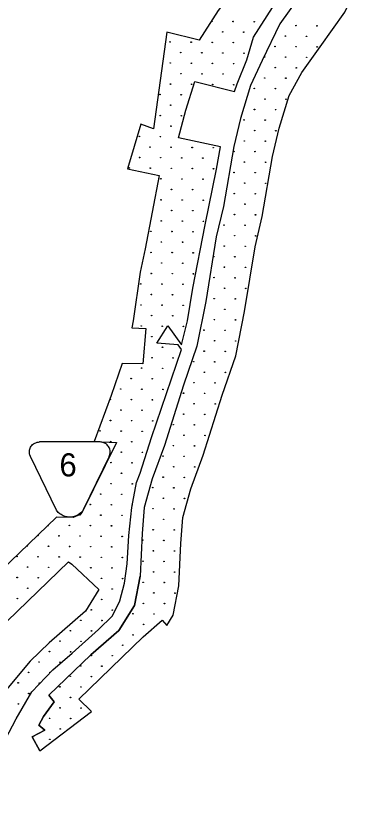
# Model space of a CAD drawing. Extents: x 1612280 to 1883141, y 560852 to 780851.
# Drawn here: x 1737209 to 1743599, y 621707 to 636137 of the extents above; entities that cross this region are included whole.
import ezdxf

# ---------------------------------------------------------------- set-up
doc = ezdxf.new("R2010")
doc.units = 0
for name, color, linetype in [('DESIGN - EROSION CONTROL - Devices', 7, 'Continuous'), ('DESIGN - ROW - Easement Linework and Patterning', 7, 'Continuous'), ('DESIGN - SCRATCH - User 1', 7, 'Continuous')]:
    doc.layers.add(name, color=color, linetype=linetype)

msp = doc.modelspace()

# ---------------------------------------------------------------- linework, layer by layer
at = {"layer": 'DESIGN - EROSION CONTROL - Devices'}
for centre in [(1740788, 636037), (1740788, 636037), (1741172, 636033), (1741172, 636033), (1741557, 636029), (1741557, 636029), (1742317, 635958), (1742317, 635958), (1742701, 635954), (1742701, 635954), (1740982, 635843), (1740982, 635843), (1741366, 635839), (1741366, 635839), (1740022, 635660), (1740022, 635660), (1740407, 635656), (1740407, 635656), (1740791, 635652), (1740791, 635652), (1741176, 635649), (1741176, 635649), (1742126, 635767), (1742126, 635767), (1742511, 635763), (1742511, 635763), (1741936, 635577), (1741936, 635577), (1742320, 635573), (1742320, 635573), (1742705, 635569), (1742705, 635569), (1740216, 635466), (1740216, 635466), (1740601, 635462), (1740601, 635462), (1740985, 635458), (1740985, 635458), (1741370, 635454), (1741370, 635454), (1741745, 635386), (1741745, 635386), (1742130, 635383), (1742130, 635383), (1742514, 635379), (1742514, 635379), (1740026, 635275), (1740026, 635275), (1740411, 635271), (1740411, 635271), (1740795, 635268), (1740795, 635268), (1741180, 635264), (1741180, 635264), (1740220, 635081), (1740220, 635081), (1740605, 635077), (1740605, 635077), (1740989, 635074), (1740989, 635074), (1741940, 635192), (1741940, 635192), (1742324, 635188), (1742324, 635188), (1741749, 635002), (1741749, 635002), (1742134, 634998), (1742134, 634998), (1740030, 634891), (1740030, 634891), (1740414, 634887), (1740414, 634887), (1740799, 634883), (1740799, 634883), (1741183, 634879), (1741183, 634879), (1741559, 634811), (1741559, 634811), (1741943, 634808), (1741943, 634808), (1739839, 634700), (1739839, 634700), (1740224, 634696), (1740224, 634696), (1741753, 634617), (1741753, 634617), (1740033, 634506), (1740033, 634506), (1742137, 634614), (1742137, 634614), (1741562, 634427), (1741562, 634427), (1741947, 634423), (1741947, 634423), (1739843, 634316), (1739843, 634316), (1740228, 634312), (1740228, 634312), (1741372, 634236), (1741372, 634236), (1741757, 634233), (1741757, 634233), (1740037, 634122), (1740037, 634122), (1741566, 634042), (1741566, 634042), (1739462, 633935), (1739462, 633935), (1739847, 633931), (1739847, 633931), (1741951, 634039), (1741951, 634039), (1741376, 633852), (1741376, 633852), (1741760, 633848), (1741760, 633848), (1739656, 633741), (1739656, 633741), (1740041, 633737), (1740041, 633737), (1740425, 633733), (1740425, 633733), (1740810, 633730), (1740810, 633730), (1741185, 633661), (1741185, 633661), (1741570, 633658), (1741570, 633658), (1739466, 633550), (1739466, 633550), (1739850, 633547), (1739850, 633547), (1740235, 633543), (1740235, 633543), (1740620, 633539), (1740620, 633539), (1741379, 633467), (1741379, 633467), (1741764, 633464), (1741764, 633464), (1739276, 633360), (1739276, 633360), (1739660, 633356), (1739660, 633356), (1740045, 633352), (1740045, 633352), (1740429, 633349), (1740429, 633349), (1740814, 633345), (1740814, 633345), (1741189, 633277), (1741189, 633277), (1741574, 633273), (1741574, 633273), (1739854, 633162), (1739854, 633162), (1740239, 633158), (1740239, 633158), (1740623, 633155), (1740623, 633155), (1741383, 633083), (1741383, 633083), (1741768, 633079), (1741768, 633079), (1740048, 632968), (1740048, 632968), (1740433, 632964), (1740433, 632964), (1741193, 632892), (1741193, 632892), (1741577, 632889), (1741577, 632889), (1739858, 632777), (1739858, 632777), (1740243, 632774), (1740243, 632774), (1740627, 632770), (1740627, 632770), (1741387, 632698), (1741387, 632698), (1740052, 632583), (1740052, 632583), (1740437, 632580), (1740437, 632580), (1741197, 632508), (1741197, 632508), (1741581, 632504), (1741581, 632504), (1739862, 632393), (1739862, 632393), (1740246, 632389), (1740246, 632389), (1740631, 632385), (1740631, 632385), (1741006, 632317), (1741006, 632317), (1741391, 632314), (1741391, 632314), (1739671, 632202), (1739671, 632202), (1740056, 632199), (1740056, 632199), (1740440, 632195), (1740440, 632195), (1741200, 632123), (1741200, 632123), (1741585, 632120), (1741585, 632120), (1739865, 632008), (1739865, 632008), (1740250, 632005), (1740250, 632005), (1741010, 631933), (1741010, 631933), (1741394, 631929), (1741394, 631929), (1739675, 631818), (1739675, 631818), (1740060, 631814), (1740060, 631814), (1740444, 631810), (1740444, 631810), (1740819, 631742), (1740819, 631742), (1741204, 631739), (1741204, 631739), (1739869, 631624), (1739869, 631624), (1740254, 631620), (1740254, 631620), (1741014, 631548), (1741014, 631548), (1741398, 631545), (1741398, 631545), (1739679, 631433), (1739679, 631433), (1740063, 631430), (1740063, 631430), (1740448, 631426), (1740448, 631426), (1740823, 631358), (1740823, 631358), (1741208, 631354), (1741208, 631354), (1739488, 631243), (1739488, 631243), (1739873, 631239), (1739873, 631239), (1740257, 631236), (1740257, 631236), (1741017, 631164), (1741017, 631164), (1741402, 631160), (1741402, 631160), (1739682, 631049), (1739682, 631049), (1740067, 631045), (1740067, 631045), (1740827, 630973), (1740827, 630973), (1741211, 630970), (1741211, 630970), (1739492, 630858), (1739492, 630858), (1739877, 630855), (1739877, 630855), (1740261, 630851), (1740261, 630851), (1741021, 630779), (1741021, 630779), (1739686, 630664), (1739686, 630664), (1740071, 630661), (1740071, 630661), (1740831, 630589), (1740831, 630589), (1741215, 630585), (1741215, 630585), (1739496, 630474), (1739496, 630474), (1739880, 630470), (1739880, 630470), (1740265, 630466), (1740265, 630466), (1740640, 630398), (1740640, 630398), (1741025, 630395), (1741025, 630395), (1739690, 630280), (1739690, 630280), (1740834, 630204), (1740834, 630204), (1741219, 630200), (1741219, 630200), (1739884, 630086), (1739884, 630086), (1740644, 630014), (1740644, 630014), (1741029, 630010), (1741029, 630010), (1739694, 629895), (1739694, 629895), (1740078, 629891), (1740078, 629891), (1740454, 629823), (1740454, 629823), (1740838, 629820), (1740838, 629820), (1739503, 629705), (1739503, 629705), (1739888, 629701), (1739888, 629701), (1740648, 629629), (1740648, 629629), (1741032, 629626), (1741032, 629626), (1739313, 629514), (1739313, 629514), (1739697, 629511), (1739697, 629511), (1740457, 629439), (1740457, 629439), (1740842, 629435), (1740842, 629435), (1739122, 629324), (1739122, 629324), (1739507, 629320), (1739507, 629320), (1739892, 629316), (1739892, 629316), (1738932, 629134), (1738932, 629134), (1740267, 629248), (1740267, 629248), (1740651, 629245), (1740651, 629245), (1739317, 629130), (1739317, 629130), (1739701, 629126), (1739701, 629126), (1740461, 629054), (1740461, 629054), (1740846, 629051), (1740846, 629051), (1739126, 628939), (1739126, 628939), (1739511, 628936), (1739511, 628936), (1740271, 628864), (1740271, 628864), (1740655, 628860), (1740655, 628860), (1738936, 628749), (1738936, 628749), (1739320, 628745), (1739320, 628745), (1739705, 628742), (1739705, 628742), (1738745, 628559), (1738745, 628559), (1740080, 628673), (1740080, 628673), (1740465, 628670), (1740465, 628670), (1739130, 628555), (1739130, 628555), (1739514, 628551), (1739514, 628551), (1740274, 628479), (1740274, 628479), (1740659, 628476), (1740659, 628476), (1738940, 628364), (1738940, 628364), (1739324, 628361), (1739324, 628361), (1740084, 628289), (1740084, 628289), (1740468, 628285), (1740468, 628285), (1739134, 628170), (1739134, 628170), (1739518, 628167), (1739518, 628167), (1738943, 627980), (1738943, 627980), (1739894, 628099), (1739894, 628099), (1740278, 628095), (1740278, 628095), (1739328, 627976), (1739328, 627976), (1740088, 627904), (1740088, 627904), (1740472, 627901), (1740472, 627901), (1739137, 627786), (1739137, 627786), (1739897, 627714), (1739897, 627714), (1740282, 627710), (1740282, 627710), (1738947, 627595), (1738947, 627595), (1739332, 627592), (1739332, 627592), (1738757, 627405), (1738757, 627405), (1739141, 627401), (1739141, 627401), (1739707, 627524), (1739707, 627524), (1740091, 627520), (1740091, 627520), (1739901, 627329), (1739901, 627329), (1740286, 627326), (1740286, 627326), (1738566, 627215), (1738566, 627215), (1738951, 627211), (1738951, 627211), (1739711, 627139), (1739711, 627139), (1740095, 627135), (1740095, 627135), (1738376, 627024), (1738376, 627024), (1738760, 627020), (1738760, 627020), (1739145, 627017), (1739145, 627017), (1738185, 626834), (1738185, 626834), (1738570, 626830), (1738570, 626830), (1738954, 626826), (1738954, 626826), (1739905, 626945), (1739905, 626945), (1739714, 626754), (1739714, 626754), (1740099, 626751), (1740099, 626751), (1737610, 626647), (1737610, 626647), (1737995, 626643), (1737995, 626643), (1738379, 626640), (1738379, 626640), (1738764, 626636), (1738764, 626636), (1739149, 626632), (1739149, 626632), (1739524, 626564), (1739524, 626564), (1739908, 626560), (1739908, 626560), (1737420, 626457), (1737420, 626457), (1737805, 626453), (1737805, 626453), (1738189, 626449), (1738189, 626449), (1738574, 626445), (1738574, 626445), (1738958, 626442), (1738958, 626442), (1737230, 626266), (1737230, 626266), (1737614, 626262), (1737614, 626262), (1737999, 626259), (1737999, 626259), (1738383, 626255), (1738383, 626255), (1738768, 626251), (1738768, 626251), (1739152, 626248), (1739152, 626248), (1739718, 626370), (1739718, 626370), (1740103, 626366), (1740103, 626366), (1739528, 626179), (1739528, 626179), (1739912, 626176), (1739912, 626176), (1737424, 626072), (1737424, 626072), (1737808, 626068), (1737808, 626068), (1738577, 626061), (1738577, 626061), (1738962, 626057), (1738962, 626057), (1739722, 625985), (1739722, 625985), (1740106, 625982), (1740106, 625982), (1737233, 625882), (1737233, 625882), (1737618, 625878), (1737618, 625878), (1738772, 625867), (1738772, 625867), (1739156, 625863), (1739156, 625863), (1737427, 625687), (1737427, 625687), (1738966, 625673), (1738966, 625673), (1739531, 625795), (1739531, 625795), (1739916, 625791), (1739916, 625791), (1739726, 625601), (1739726, 625601), (1740110, 625597), (1740110, 625597), (1737237, 625497), (1737237, 625497), (1738775, 625482), (1738775, 625482), (1739535, 625410), (1739535, 625410), (1739920, 625407), (1739920, 625407), (1738585, 625292), (1738585, 625292), (1738969, 625288), (1738969, 625288), (1738394, 625101), (1738394, 625101), (1738779, 625098), (1738779, 625098), (1739345, 625220), (1739345, 625220), (1739729, 625216), (1739729, 625216), (1739539, 625026), (1739539, 625026), (1738204, 624911), (1738204, 624911), (1738589, 624907), (1738589, 624907), (1739348, 624835), (1739348, 624835), (1738014, 624721), (1738014, 624721), (1738398, 624717), (1738398, 624717), (1737823, 624530), (1737823, 624530), (1738208, 624526), (1738208, 624526), (1739158, 624645), (1739158, 624645), (1738583, 624458), (1738583, 624458), (1738968, 624455), (1738968, 624455), (1737633, 624340), (1737633, 624340), (1738017, 624336), (1738017, 624336), (1738393, 624268), (1738393, 624268), (1738777, 624264), (1738777, 624264), (1737442, 624149), (1737442, 624149), (1737252, 623959), (1737252, 623959), (1737637, 623955), (1737637, 623955), (1738202, 624078), (1738202, 624078), (1738587, 624074), (1738587, 624074), (1738012, 623887), (1738012, 623887), (1738396, 623883), (1738396, 623883), (1737446, 623765), (1737446, 623765), (1738206, 623693), (1738206, 623693), (1737256, 623574), (1737256, 623574), (1738016, 623503), (1738016, 623503), (1738400, 623499), (1738400, 623499), (1737825, 623312), (1737825, 623312), (1738210, 623308), (1738210, 623308), (1738019, 623118), (1738019, 623118), (1737829, 622928), (1737829, 622928)]:
    msp.add_circle(centre, 5.28, dxfattribs=at)
for centre, start, end in [((1742895, 635760), 79.1429, 209.9823), ((1741002, 632702), 316.6022, 24.0796), ((1739119, 629708), 298.3834, 22.7238), ((1739335, 627207), 98.739, 240.4954), ((1737801, 626837), 182.3755, 85.4116), ((1739154, 625030), 294.704, 1.32), ((1738773, 624649), 295.7374, 326.2899), ((1737827, 624146), 9.15, 263.6958), ((1737638, 622737), 233.0313, 181.755)]:
    msp.add_arc(centre, 5.28, start, end, dxfattribs=at)
at = {"layer": 'DESIGN - ROW - Easement Linework and Patterning'}
for points in [[(1737949, 627112), (1737475, 628092), (1737464, 628119), (1737460, 628137), (1737457, 628155), (1737456, 628171), (1737457, 628188), (1737459, 628205), (1737465, 628228), (1737472, 628246), (1737479, 628262), (1737489, 628278), (1737500, 628292), (1737515, 628308), (1737529, 628320), (1737543, 628329), (1737555, 628336), (1737572, 628344), (1737588, 628350), (1737600, 628353), (1737622, 628356), (1737641, 628357)], [(1737949, 627112), (1737475, 628092), (1737464, 628119), (1737460, 628137), (1737457, 628155), (1737456, 628171), (1737457, 628188), (1737459, 628205), (1737465, 628228), (1737472, 628246), (1737479, 628262), (1737489, 628278), (1737500, 628292), (1737515, 628308), (1737529, 628320), (1737543, 628329), (1737555, 628336), (1737572, 628344), (1737588, 628350), (1737600, 628353), (1737622, 628356), (1737641, 628357)], [(1738912, 628092), (1738918, 628110), (1738926, 628133), (1738929, 628150), (1738930, 628170), (1738930, 628185), (1738928, 628203), (1738923, 628226), (1738916, 628244), (1738909, 628258), (1738901, 628273), (1738889, 628289), (1738876, 628303), (1738858, 628320), (1738843, 628330), (1738829, 628338), (1738815, 628344), (1738798, 628350), (1738779, 628355), (1738765, 628356), (1738746, 628358), (1737641, 628357)], [(1738912, 628092), (1738918, 628110), (1738926, 628133), (1738929, 628150), (1738930, 628170), (1738930, 628185), (1738928, 628203), (1738923, 628226), (1738916, 628244), (1738909, 628258), (1738901, 628273), (1738889, 628289), (1738876, 628303), (1738858, 628320), (1738843, 628330), (1738829, 628338), (1738815, 628344), (1738798, 628350), (1738779, 628355), (1738765, 628356), (1738746, 628358), (1737641, 628357)], [(1738912, 628092), (1738439, 627115), (1738424, 627094), (1738409, 627078), (1738396, 627065), (1738368, 627042), (1738346, 627027), (1738322, 627014), (1738289, 627001), (1738251, 626991), (1738220, 626986), (1738185, 626985), (1738147, 626989), (1738107, 626998), (1738071, 627011), (1738035, 627030), (1738013, 627045), (1737984, 627071), (1737949, 627112)], [(1738912, 628092), (1738439, 627115), (1738424, 627094), (1738409, 627078), (1738396, 627065), (1738368, 627042), (1738346, 627027), (1738322, 627014), (1738289, 627001), (1738251, 626991), (1738220, 626986), (1738185, 626985), (1738147, 626989), (1738107, 626998), (1738071, 627011), (1738035, 627030), (1738013, 627045), (1737984, 627071), (1737949, 627112)]]:
    msp.add_lwpolyline(points, dxfattribs=at)
at = {"layer": 'DESIGN - SCRATCH - User 1'}
for points in [[(1741051, 637528), (1741178, 637245), (1741316, 636895), (1741331, 636815), (1741302, 636760), (1740900, 636237), (1740553, 635691)], [(1741051, 637528), (1741178, 637245), (1741316, 636895), (1741331, 636815), (1741302, 636760), (1740900, 636237), (1740553, 635691)], [(1743351, 637284), (1743407, 637509), (1743316, 637538), (1742882, 636928), (1742337, 636428), (1742024, 635990), (1741703, 635322), (1741490, 634865), (1741309, 634264), (1741185, 633749), (1740999, 632656)], [(1743351, 637284), (1743407, 637509), (1743316, 637538), (1742882, 636928), (1742337, 636428), (1742024, 635990), (1741703, 635322), (1741490, 634865), (1741309, 634264), (1741185, 633749), (1740999, 632656)], [(1741705, 632476), (1741891, 633568), (1742015, 634084), (1742197, 634685), (1742425, 635105), (1742759, 635572), (1743207, 636202), (1743532, 636880), (1743599, 637220), (1743351, 637284)], [(1741705, 632476), (1741891, 633568), (1742015, 634084), (1742197, 634685), (1742425, 635105), (1742759, 635572), (1743207, 636202), (1743532, 636880), (1743599, 637220), (1743351, 637284)], [(1740665, 632320), (1740869, 633340), (1740940, 633743), (1740176, 633909), (1740312, 634416), (1740471, 634939), (1741198, 634757), (1741245, 634896), (1741421, 635332), (1741541, 635745), (1741888, 636286), (1742121, 636726), (1742053, 637162)], [(1740665, 632320), (1740869, 633340), (1740940, 633743), (1740176, 633909), (1740312, 634416), (1740471, 634939), (1741198, 634757), (1741245, 634896), (1741421, 635332), (1741541, 635745), (1741888, 636286), (1742121, 636726), (1742053, 637162)], [(1740553, 635691), (1739961, 635839), (1739723, 634072), (1739492, 634161), (1739248, 633344), (1739821, 633219)], [(1740553, 635691), (1739961, 635839), (1739723, 634072), (1739492, 634161), (1739248, 633344), (1739821, 633219)], [(1739821, 633219), (1739569, 631885), (1739479, 631458)], [(1739821, 633219), (1739569, 631885), (1739479, 631458)], [(1740999, 632656), (1740866, 632103), (1740675, 630920), (1740513, 630108), (1740265, 629393), (1739921, 628295), (1739693, 627685), (1739550, 627160), (1739511, 626683), (1739475, 625908)], [(1740999, 632656), (1740866, 632103), (1740675, 630920), (1740513, 630108), (1740265, 629393), (1739921, 628295), (1739693, 627685), (1739550, 627160), (1739511, 626683), (1739475, 625908)], [(1740181, 625728), (1740218, 626502), (1740256, 626979), (1740399, 627504), (1740628, 628115), (1740971, 629212), (1741219, 629928), (1741381, 630739), (1741572, 631922), (1741705, 632476)], [(1740181, 625728), (1740218, 626502), (1740256, 626979), (1740399, 627504), (1740628, 628115), (1740971, 629212), (1741219, 629928), (1741381, 630739), (1741572, 631922), (1741705, 632476)], [(1739325, 627161), (1739408, 627615), (1739476, 627789), (1739681, 628440), (1740233, 630044), (1740171, 630133), (1739778, 630160), (1739980, 630479), (1740231, 630131), (1740339, 630567), (1740437, 631165), (1740665, 632320)], [(1739325, 627161), (1739408, 627615), (1739476, 627789), (1739681, 628440), (1740233, 630044), (1740171, 630133), (1739778, 630160), (1739980, 630479), (1740231, 630131), (1740339, 630567), (1740437, 631165), (1740665, 632320)], [(1739479, 631458), (1739347, 630571), (1739326, 630439), (1739579, 630428), (1739523, 629784), (1739151, 629788), (1738945, 629204), (1738636, 628363)], [(1739479, 631458), (1739347, 630571), (1739326, 630439), (1739579, 630428), (1739523, 629784), (1739151, 629788), (1738945, 629204), (1738636, 628363)], [(1738636, 628363), (1739044, 628350), (1738420, 627078), (1738383, 627034), (1738254, 626975)], [(1738636, 628363), (1739044, 628350), (1738420, 627078), (1738383, 627034), (1738254, 626975)], [(1737022, 622929), (1737218, 623300), (1737499, 623797), (1737882, 624199), (1738237, 624500), (1738714, 624935), (1738972, 625181), (1739106, 625459), (1739191, 625782), (1739241, 626133), (1739268, 626649), (1739325, 627161)], [(1737022, 622929), (1737218, 623300), (1737499, 623797), (1737882, 624199), (1738237, 624500), (1738714, 624935), (1738972, 625181), (1739106, 625459), (1739191, 625782), (1739241, 626133), (1739268, 626649), (1739325, 627161)], [(1738254, 626975), (1737950, 626985), (1735256, 624393), (1735803, 623789)], [(1738254, 626975), (1737950, 626985), (1735256, 624393), (1735803, 623789)], [(1736818, 623785), (1736298, 624359), (1738169, 626169), (1738231, 626123), (1738723, 625661), (1738477, 625268), (1737819, 624690)], [(1736818, 623785), (1736298, 624359), (1738169, 626169), (1738231, 626123), (1738723, 625661), (1738477, 625268), (1737819, 624690)], [(1737644, 622716), (1737510, 622974), (1737739, 623093), (1737630, 623189), (1737715, 623346), (1737911, 623613), (1737811, 623733), (1738578, 624472), (1739089, 624916), (1739375, 625374), (1739475, 625908)], [(1739475, 625908), (1739375, 625374), (1739089, 624916), (1738578, 624472), (1737811, 623733), (1737911, 623613), (1737715, 623346), (1737630, 623189), (1737739, 623093), (1737510, 622974), (1737644, 622716)], [(1737644, 622716), (1737510, 622974), (1737739, 623093), (1737630, 623189), (1737715, 623346), (1737911, 623613), (1737811, 623733), (1738578, 624472), (1739089, 624916), (1739375, 625374), (1739475, 625908)], [(1739475, 625908), (1739375, 625374), (1739089, 624916), (1738578, 624472), (1737811, 623733), (1737911, 623613), (1737715, 623346), (1737630, 623189), (1737739, 623093), (1737510, 622974), (1737644, 622716)], [(1739877, 625105), (1739966, 625008), (1740081, 625194), (1740181, 625728)], [(1739877, 625105), (1739966, 625008), (1740081, 625194), (1740181, 625728)], [(1739531, 624799), (1739877, 625105)], [(1739531, 624799), (1739877, 625105)], [(1737819, 624690), (1737472, 624355), (1736911, 623689), (1736402, 622911), (1735867, 621975), (1735915, 621707)], [(1737819, 624690), (1737472, 624355), (1736911, 623689), (1736402, 622911), (1735867, 621975), (1735915, 621707)], [(1738356, 623661), (1739531, 624799)], [(1738356, 623661), (1739531, 624799)], [(1738591, 623434), (1738356, 623661)], [(1738591, 623434), (1738356, 623661)], [(1737644, 622716), (1738591, 623434)], [(1737644, 622716), (1738591, 623434)]]:
    msp.add_lwpolyline(points, dxfattribs=at)

# ---------------------------------------------------------------- texts
at = {"layer": 'DESIGN - ROW - Easement Linework and Patterning'}
msp.add_text('6', height=422, rotation=0.0012, dxfattribs=at).set_placement((1738005, 627728))
msp.add_text('6', height=422, rotation=0.0012, dxfattribs=at).set_placement((1738005, 627728))

doc.saveas('drawing.dxf')
